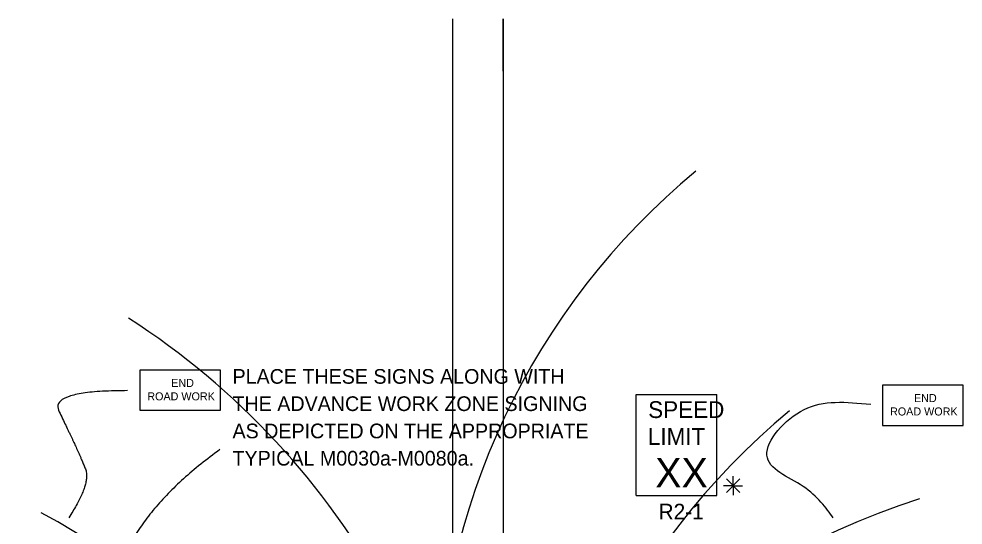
# Model space of a CAD drawing. Extents: x 16552 to 19508, y 5713 to 7079.
# Drawn here: x 16774.1 to 17223.8, y 6732.8 to 6974.1 of the extents above; entities that cross this region are included whole.
import ezdxf

# ---------------------------------------------------------------- set-up
doc = ezdxf.new("R2010")
doc.units = 0
for name, color, linetype in [('ALI_LEGAL_EX', 7, 'Continuous'), ('PAVT_EDGE_EX', 7, 'Continuous'), ('TRAFFIC_SIGNS_PR', 7, 'Continuous'), ('TYPICAL_TEXT_DIMEN_PR', 7, 'Continuous')]:
    doc.layers.add(name, color=color, linetype=linetype)

msp = doc.modelspace()

# ---------------------------------------------------------------- linework, layer by layer
at = {"layer": 'ALI_LEGAL_EX'}
for p, q in [((16980.68, 6974.12), (16980.68, 6155.98)), ((17004.68, 6974.12), (17004.68, 6155.98)), ((16980.68, 6877.04), (16980.68, 6013.12)), ((17004.68, 6877.04), (17004.68, 6013.12))]:
    msp.add_line(p, q, dxfattribs=at)
msp.add_lwpolyline([(17004.68, 6949.12), (17004.68, 6974.12)], dxfattribs=at)
for centre, radius, start, end in [((17313.01, 6639.38), 340, 129.5666, 180), ((16629.65, 6525.15), 364, 0, 57.2958), ((17357.65, 6525.15), 340, 129.5666, 180)]:
    msp.add_arc(centre, radius, start, end, dxfattribs=at)
at = {"layer": 'PAVT_EDGE_EX'}
for centre, radius, start, end in [((17319.93, 6383.76), 380, 107.923, 157.5011), ((16591.93, 6383.76), 404, 21.0961, 61.4862)]:
    msp.add_arc(centre, radius, start, end, dxfattribs=at)
at = {"layer": 'TRAFFIC_SIGNS_PR'}
for p, q in [((17068.03, 6795.04), (17106.43, 6795.04)), ((17068.03, 6747.04), (17068.03, 6795.04)), ((17106.43, 6747.04), (17106.43, 6795.04)), ((17068.03, 6747.04), (17106.43, 6747.04))]:
    msp.add_line(p, q, dxfattribs=at)
for points in [[(16831.68, 6787.57), (16870.08, 6787.57), (16870.08, 6806.77), (16831.68, 6806.77)], [(17185.35, 6780.35), (17223.75, 6780.35), (17223.75, 6799.55), (17185.35, 6799.55)], [(17185.35, 6780.35), (17223.75, 6780.35), (17223.75, 6799.55), (17185.35, 6799.55)]]:
    msp.add_lwpolyline(points, close=True, dxfattribs=at)
at = {"layer": 'TYPICAL_TEXT_DIMEN_PR'}
for p, q in [((17111.05, 6754.84), (17117.43, 6748.46)), ((17117.43, 6754.84), (17111.05, 6748.46)), ((17114.24, 6751.65), (17114.24, 6756.11)), ((17114.24, 6751.65), (17109.71, 6751.65)), ((17114.24, 6751.65), (17117.43, 6751.65)), ((17114.24, 6751.65), (17118.72, 6751.65)), ((17114.24, 6751.65), (17114.24, 6747.15))]:
    msp.add_line(p, q, dxfattribs=at)
for points, degree in [([(16825.93, 6796.94), (16788.53, 6796.94), (16797.88, 6777.47), (16802.91, 6766.65), (16808.67, 6752.95), (16797.88, 6736.37)], 2), ([(17161.84, 6736.37), (17158.58, 6740.95), (17150.4, 6752.41), (17121.07, 6762.84), (17147.39, 6793.51), (17167.61, 6791.6), (17179.82, 6790.45)], 3), ([(16869.81, 6768.82), (16825.93, 6737.09), (16811.54, 6666.42), (16817.3, 6656.33), (16774.14, 6631.09)], 2)]:
    msp.add_open_spline(points, degree=degree, dxfattribs=at)

# ---------------------------------------------------------------- texts
at = {"layer": 'TRAFFIC_SIGNS_PR'}
for s, height, p in [('PLACE THESE SIGNS ALONG WITH', 7, (16875.86, 6800.23)), ('END', 3.831, (16846.68, 6798.69)), ('ROAD WORK', 3.831, (16835.29, 6792.31)), ('THE ADVANCE WORK ZONE SIGNING', 7, (16875.86, 6787.23)), ('END', 3.831, (17200.35, 6791.48)), ('END', 3.831, (17200.36, 6791.49)), ('SPEED', 8, (17073.8, 6783.9)), ('ROAD WORK', 3.831, (17188.96, 6785.1)), ('ROAD WORK', 3.831, (17188.96, 6785.1)), ('AS DEPICTED ON THE APPROPRIATE', 7, (16875.86, 6774.23)), ('LIMIT', 8, (17073.64, 6771.1)), ('TYPICAL M0030a-M0080a.', 7, (16875.86, 6761.23)), ('XX', 14.031, (17077.14, 6750.79)), ('R2-1', 7.44, (17078.71, 6735.6))]:
    msp.add_text(s, height=height, dxfattribs=at).set_placement(p)

doc.saveas('drawing.dxf')
